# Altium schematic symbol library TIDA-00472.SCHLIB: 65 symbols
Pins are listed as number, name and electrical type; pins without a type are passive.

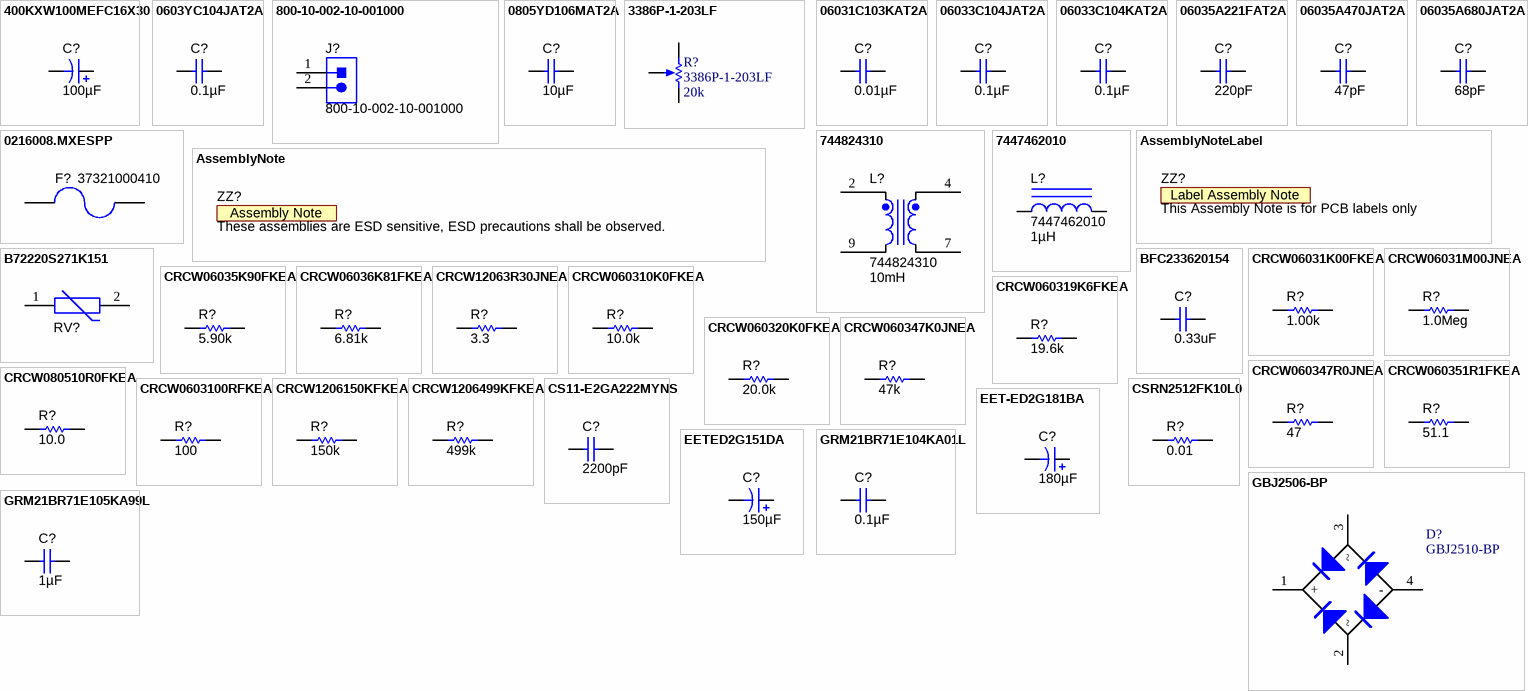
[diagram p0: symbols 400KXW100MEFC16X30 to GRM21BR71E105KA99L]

## 400KXW100MEFC16X30
designator C?  ValueDisplayed: 100µF  (hidden comment: 400KXW100MEFC16X30)
CAP, AL, 100 µF, 400 V, +/- 20%, TH; Manufacturer: Rubycon; Polarized: Y; CompType: Capacitor; Value: 100uF; U/M: EA; Cap_F: 0.0001; Tolerance_%: 20; Value1: Unknown; VDC_V: 400; Value2: 400V; IRMS_A: 0.58; TaMin_C: -25; TaMax_C: 105; Cap_Case: RCAP, 16x30mm
signal-integrity model Cap
simulation model Cap
footprint CAPPR750W80D1600H3000
footprint CAPPR750W80D1600H3000_HU
footprint CAPPR750W80D1600H3000_HD
pins: 1 +, 2 -

## 0603YC104JAT2A
designator C?  ValueDisplayed: 0.1µF  (hidden comment: 0603YC104JAT2A)
CAP, CERM, 0.1uF, 16V, +/-5%, X7R, 0603; Manufacturer: AVX; Polarized: N; CompType: Capacitor; U/M: EA; Cap_F: 0.0000001; Tolerance_%: 5; ESR_Ohm: 0.039; Value1: 0.039 ohm; VDC_V: 16; TaMin_C: -55; TaMax_C: 125; Cap_Case: 0603
signal-integrity model Cap
simulation model Cap
footprint 0603
footprint 0603M
footprint 0603L
footprint 0603_HV
footprint 0603S
pins: 1, 2

## 800-10-002-10-001000
designator J?
Header, 100mil, 2x1, TH; Manufacturer: Mill-Max; SymbolCreator: a0412235; U/M: EA
footprint Mill-Max_800-10-002-10-001000
pins: 1, 2
1 alternate drawing of the same symbol

## 0805YD106MAT2A
designator C?  ValueDisplayed: 10µF  (hidden comment: 0805YD106MAT2A)
CAP, CERM, 10uF, 16V, +/-20%, X5R, 0805; Manufacturer: AVX; Polarized: N; CompType: Capacitor; U/M: EA; Cap_F: 0.00001; Tolerance_%: 20; Value1: Unknown; VDC_V: 16; TaMin_C: -55; TaMax_C: 85; Cap_Case: 0805
signal-integrity model Cap
simulation model Cap
footprint 0805_HV
footprint 0805
footprint 0805M
footprint 0805L
pins: 1, 2

## 3386P-1-203LF
designator R?  value 20k
TRIMMER, 20k ohm, 0.5W, TH; Manufacturer: Bourns; Sim Note: Enter the Resistance value and the set point into parameter fields.; SymbolCreator: a0412235
simulation model POT (Potentiometer)
footprint BOURNS_3386P
pins: 1 CCW, 2 WIPER, 3 CW
1 alternate drawing of the same symbol

## 06031C103KAT2A
designator C?  ValueDisplayed: 0.01µF  (hidden comment: 06031C103KAT2A)
CAP, CERM, 0.01uF, 100V, +/-10%, X7R, 0603; Manufacturer: AVX; Polarized: N; CompType: Capacitor; U/M: EA; Cap_F: 0.00000001; Tolerance_%: 10; ESR_Ohm: 0.098; Value1: 0.098 ohm; VDC_V: 100; TaMin_C: -55; TaMax_C: 125; Cap_Case: 0603
signal-integrity model Cap
simulation model Cap
footprint 0603
footprint 0603M
footprint 0603L
footprint 0603_HV
footprint 0603S
pins: 1, 2

## 06033C104JAT2A
designator C?  ValueDisplayed: 0.1µF  (hidden comment: 06033C104JAT2A)
CAP, CERM, 0.1uF, 25V, +/-5%, X7R, 0603; Manufacturer: AVX; Polarized: N; CompType: Capacitor; U/M: EA; Cap_F: 0.0000001; Tolerance_%: 5; ESR_Ohm: 0.05; Value1: 0.05 ohm; VDC_V: 25; TaMin_C: -55; TaMax_C: 125; Cap_Case: 0603
signal-integrity model Cap
simulation model Cap
footprint 0603
footprint 0603M
footprint 0603L
footprint 0603_HV
footprint 0603S
pins: 1, 2

## 06033C104KAT2A
designator C?  ValueDisplayed: 0.1µF  (hidden comment: 06033C104KAT2A)
CAP, CERM, 0.1 µF, 25 V, +/- 10%, X7R, 0603; Manufacturer: AVX; Polarized: N; CompType: Capacitor; Value: 0.1uF; U/M: EA; Cap_F: 0.0000001; Tolerance_%: 10; ESR_ohm: 0.05; Value1: 0.05 ohm; VDC_V: 25; Value2: 25V; TaMin_C: -55; TaMax_C: 125; Cap_Case: 0603
signal-integrity model Cap
simulation model Cap
footprint 0603
footprint 0603M
footprint 0603L
footprint 0603_HV
footprint 0603S
pins: 1, 2

## 06035A221FAT2A
designator C?  ValueDisplayed: 220pF  (hidden comment: 06035A221FAT2A)
CAP, CERM, 220 pF, 50 V, +/- 1%, C0G/NP0, 0603; Manufacturer: AVX; Polarized: N; CompType: Capacitor; Value: 220pF; U/M: EA; Cap_F: 0.00000000022; Tolerance_%: 1; ESR_ohm: 0.083; Value1: 0.083 ohm; VDC_V: 50; Value2: 50V; TaMin_C: -55; TaMax_C: 125; Cap_Case: 0603
signal-integrity model Cap
simulation model Cap
footprint 0603
footprint 0603M
footprint 0603L
footprint 0603_HV
footprint 0603S
pins: 1, 2

## 06035A470JAT2A
designator C?  ValueDisplayed: 47pF  (hidden comment: 06035A470JAT2A)
CAP, CERM, 47 pF, 50 V, +/- 5%, C0G/NP0, 0603; Manufacturer: AVX; Polarized: N; CompType: Capacitor; Value: 47pF; U/M: EA; Cap_F: 0.000000000047; Tolerance_%: 5; ESR_ohm: 0.174; Value1: 0.174 ohm; VDC_V: 50; Value2: 50V; TaMin_C: -55; TaMax_C: 125; Cap_Case: 0603
signal-integrity model Cap
simulation model Cap
footprint 0603
footprint 0603M
footprint 0603L
footprint 0603_HV
footprint 0603S
pins: 1, 2

## 06035A680JAT2A
designator C?  ValueDisplayed: 68pF  (hidden comment: 06035A680JAT2A)
CAP, CERM, 68pF, 50V, +/-5%, C0G/NP0, 0603; Manufacturer: AVX; Polarized: N; CompType: Capacitor; U/M: EA; Cap_F: 0.000000000068; Tolerance_%: 5; ESR_Ohm: 0.144; Value1: 0.144 ohm; VDC_V: 50; TaMin_C: -55; TaMax_C: 125; Cap_Case: 0603
signal-integrity model Cap
simulation model Cap
footprint 0603
footprint 0603M
footprint 0603L
footprint 0603_HV
footprint 0603S
pins: 1, 2

## 0216008.MXESPP
designator F?, comment 37321000410
FUSE BOARD MNT 10A 250VAC RADIAL; Manufacturer: Littelfuse Inc; U/M: EA; VDC_V: 250; Irating_A: 8; Rtyp_Ohm: 0.0123; Soldering_Wave_MaxTemp_C: 260; Soldering_Wave_MaxTime_s: 5
footprint FUSE_37321000430 (LITTELFUSE_373, TH-2P)
footprint CAPPRD1000W150D3500H5000 (Panasonic)
footprint CAPPR2-5x11 (Capacitor, Electrolytic, Radial; Body 5 x 11 mm (Dia.xH typ); Pin Spacing 2 mm (typ))
pins: 1, 2

## 744824310
designator L?  ValueDisplayed: 10mH
Coupled inductor, 10 mH, 3 A, 0.105 ohm, +/- 30%, TH; Manufacturer: Wurth Elektronik eiSos; SymbolCreator: a0799628; Ind_H: 10.0E-3; DCR_ohm: 0.105; Isat: 3; Tolerance_%: 30; Value: 10mH
footprint IND_WE-CMB_L
pins: 2, 4, 7, 9

## 7447462010
designator L?  ValueDisplayed: 1µH
Inductor, Unshielded Drum Core, Ferrite, 1uH, 8A, 0.006 ohm, TH; Manufacturer: Wurth Elektronik eiSos; Ind_H: 1.0E-6; Imax_A: 8; Irms: 8.5A @ 40C rise; Isat: 8A @ 10% inductance drop; DCR_ohm: 0.006; U/M: EA
signal-integrity model Inductor
simulation model Inductor
footprint IND_WE-TI_XS
footprint CAPPRD1000W150D3500H5000 (Panasonic)
footprint CAPPR2-5x11 (Capacitor, Electrolytic, Radial; Body 5 x 11 mm (Dia.xH typ); Pin Spacing 2 mm (typ))
pins: 1, 2

## AssemblyNote
designator ZZ?, comment These assemblies are ESD sensitive, ESD precautions shall be observed.  (no BOM)
SymbolCreator: codlsc; CompType: AssemblyNote
footprint AssemblyNote

## AssemblyNoteLabel
designator ZZ?, comment This Assembly Note is for PCB labels only  (no BOM)
SymbolCreator: a0412235
footprint AssemblyNoteLabel

## B72220S271K151
designator RV?  (value not drawn)
VARISTOR, 387V, 8KA, DISC 20MM; Manufacturer: EPCOS Inc; SymbolCreator: x0199378
footprint VAR_B72220S0271K151 (VARISTOR, 275V, 8KA, DISC 20MM)
footprint VAR_B72220S0271K151 (VARISTOR, 275V, 8KA, DISC 20MM)
pins: 1, 2

## BFC233620154
designator C?, comment value 0.33uF  (hidden comment: B32922C3334M189)
CAP FILM 0.33UF 630VDC RADIAL; Manufacturer: EPCOS(TDK); CompType: Film Capacitor; SymbolCreator: x0199378
footprint B32922_12mm (Epcos film capacitors, 15mm spacing)
pins: 1, 2

## CRCW06031K00FKEA
designator R?  ValueDisplayed: 1.00k  (hidden comment: CRCW06031K00FKEA)
RES, 1.00 k, 1%, 0.1 W, 0603; Manufacturer: Vishay-Dale; CompType: Resistor; Value: 1.00k; Res_ohm: 1000; Value_Code: 1k00; Tolerance_%: 1; Power_W: 0.1; Value2: 0.1W; VDC_V: 75; TempCo: 100 ppm/C; EIA_Code: E96; U/M: EA
signal-integrity model Resistor
simulation model Resistor
footprint 0603
footprint 0603M
footprint 0603L
footprint 0603_HV
footprint 0603S
pins: 1, 2

## CRCW06031M00JNEA
designator R?  value 1.0Meg  (hidden comment: CRCW06031M00JNEA)
RES, 1.0Meg ohm, 5%, 0.1W, 0603; Manufacturer: Vishay-Dale; CompType: Resistor; Res_ohm: 1000000; Value_Code: 1M00; Tolerance_%: 5; Power_W: 0.1; VDC_V: 75; TempCo: 200 ppm/C; EIA_Code: E24; U/M: EA
signal-integrity model Resistor
simulation model Resistor
footprint 0603
footprint 0603M
footprint 0603L
footprint 0603_HV
footprint 0603S
pins: 1, 2

## CRCW06035K90FKEA
designator R?  ValueDisplayed: 5.90k  (hidden comment: CRCW06035K90FKEA)
RES, 5.90 k, 1%, 0.1 W, 0603; Manufacturer: Vishay-Dale; CompType: Resistor; Res_ohm: 5900; Value: 5.90k; Value_Code: 5k90; Tolerance_%: 1; Power_W: 0.1; Value2: 0.1W; VDC_V: 75; TempCo: 100 ppm/C; EIA_Code: E96; U/M: EA
signal-integrity model Resistor
simulation model Resistor
footprint 0603
footprint 0603M
footprint 0603L
footprint 0603_HV
footprint 0603S
pins: 1, 2

## CRCW06036K81FKEA
designator R?  ValueDisplayed: 6.81k  (hidden comment: CRCW06036K81FKEA)
RES, 6.81 k, 1%, 0.1 W, 0603; Manufacturer: Vishay-Dale; CompType: Resistor; Value: 6.81k; Res_ohm: 6810; Value_Code: 6k81; Tolerance_%: 1; Power_W: 0.1; Value2: 0.1W; VDC_V: 75; TempCo: 100 ppm/C; EIA_Code: E96; U/M: EA
signal-integrity model Resistor
simulation model Resistor
footprint 0603
footprint 0603M
footprint 0603L
footprint 0603_HV
footprint 0603S
pins: 1, 2

## CRCW12063R30JNEA
designator R?  value 3.3  (hidden comment: CRCW12063R30JNEA)
RES, 3.3 ohm, 5%, 0.25W, 1206; Manufacturer: Vishay-Dale; CompType: Resistor; Value_Code: 3R30; Tolerance_%: 5; Power_W: 0.25; VDC_V: 200; TempCo: 200 ppm/C; EIA_Code: E24; U/M: EA
signal-integrity model Resistor
simulation model Resistor
footprint 1206
footprint 1206M
footprint 1206L
pins: 1, 2

## CRCW060310K0FKEA
designator R?  ValueDisplayed: 10.0k  (hidden comment: CRCW060310K0FKEA)
RES, 10.0 k, 1%, 0.1 W, 0603; Manufacturer: Vishay-Dale; CompType: Resistor; Value: 10.0k; Res_ohm: 10000; Value_Code: 10k0; Tolerance_%: 1; Power_W: 0.1; Value2: 0.1W; VDC_V: 75; TempCo: 100 ppm/C; EIA_Code: E96; U/M: EA
signal-integrity model Resistor
simulation model Resistor
footprint 0603
footprint 0603M
footprint 0603L
footprint 0603_HV
footprint 0603S
pins: 1, 2

## CRCW060319K6FKEA
designator R?  ValueDisplayed: 19.6k  (hidden comment: CRCW060319K6FKEA)
RES, 19.6 k, 1%, 0.1 W, 0603; Manufacturer: Vishay-Dale; CompType: Resistor; Value: 19.6k; Res_ohm: 19600; Value_Code: 19k6; Tolerance_%: 1; Power_W: 0.1; Value2: 0.1W; VDC_V: 75; TempCo: 100 ppm/C; EIA_Code: E96; U/M: EA
signal-integrity model Resistor
simulation model Resistor
footprint 0603
footprint 0603M
footprint 0603L
footprint 0603_HV
footprint 0603S
pins: 1, 2

## CRCW060320K0FKEA
designator R?  value 20.0k  (hidden comment: CRCW060320K0FKEA)
RES, 20.0k ohm, 1%, 0.1W, 0603; Manufacturer: Vishay-Dale; CompType: Resistor; Res_ohm: 20000; Value_Code: 20k0; Tolerance_%: 1; Power_W: 0.1; VDC_V: 75; TempCo: 100 ppm/C; EIA_Code: E96; U/M: EA
signal-integrity model Resistor
simulation model Resistor
footprint 0603
footprint 0603M
footprint 0603L
footprint 0603_HV
footprint 0603S
pins: 1, 2

## CRCW060347K0JNEA
designator R?  value 47k  (hidden comment: CRCW060347K0JNEA)
RES, 47k ohm, 5%, 0.1W, 0603; Manufacturer: Vishay-Dale; CompType: Resistor; Res_ohm: 47000; Value_Code: 47k0; Tolerance_%: 5; Power_W: 0.1; VDC_V: 75; TempCo: 200 ppm/C; EIA_Code: E24; U/M: EA
signal-integrity model Resistor
simulation model Resistor
footprint 0603
footprint 0603M
footprint 0603L
footprint 0603_HV
footprint 0603S
pins: 1, 2

## CRCW060347R0JNEA
designator R?  ValueDisplayed: 47  (hidden comment: CRCW060347R0JNEA)
RES, 47, 5%, 0.1 W, 0603; Manufacturer: Vishay-Dale; CompType: Resistor; Value: 47; Value_Code: 47R0; Tolerance_%: 5; Power_W: 0.1; Value2: 0.1W; VDC_V: 75; TempCo: 200 ppm/C; EIA_Code: E24; U/M: EA
signal-integrity model Resistor
simulation model Resistor
footprint 0603
footprint 0603M
footprint 0603L
footprint 0603_HV
footprint 0603S
pins: 1, 2

## CRCW060351R1FKEA
designator R?  ValueDisplayed: 51.1  (hidden comment: CRCW060351R1FKEA)
RES, 51.1, 1%, 0.1 W, 0603; Manufacturer: Vishay-Dale; CompType: Resistor; Value: 51.1; Value_Code: 51R1; Tolerance_%: 1; Power_W: 0.1; Value2: 0.1W; VDC_V: 75; TempCo: 100 ppm/C; EIA_Code: E96; U/M: EA
signal-integrity model Resistor
simulation model Resistor
footprint 0603
footprint 0603M
footprint 0603L
footprint 0603_HV
footprint 0603S
pins: 1, 2

## CRCW080510R0FKEA
designator R?  ValueDisplayed: 10.0  (hidden comment: CRCW080510R0FKEA)
RES, 10.0, 1%, 0.125 W, 0805; Manufacturer: Vishay-Dale; CompType: Resistor; Value: 10.0; Res_ohm: 10; Value_Code: 10R0; Tolerance_%: 1; Power_W: 0.125; Value2: 0.125W; VDC_V: 150; TempCo: 100 ppm/C; EIA_Code: E96; U/M: EA
signal-integrity model Resistor
simulation model Resistor
footprint 0805_HV
footprint 0805
footprint 0805M
footprint 0805L
pins: 1, 2

## CRCW0603100RFKEA
designator R?  ValueDisplayed: 100  (hidden comment: CRCW0603100RFKEA)
RES, 100, 1%, 0.1 W, 0603; Manufacturer: Vishay-Dale; CompType: Resistor; Value: 100; Value_Code: 100R; Tolerance_%: 1; Power_W: 0.1; Value2: 0.1W; VDC_V: 75; TempCo: 100 ppm/C; EIA_Code: E96; U/M: EA
signal-integrity model Resistor
simulation model Resistor
footprint 0603
footprint 0603M
footprint 0603L
footprint 0603_HV
footprint 0603S
pins: 1, 2

## CRCW1206150KFKEA
designator R?  value 150k  (hidden comment: CRCW1206150KFKEA)
RES, 150k ohm, 1%, 0.25W, 1206; Manufacturer: Vishay-Dale; CompType: Resistor; Res_ohm: 150000; Tolerance_%: 1; Power_W: 0.25; VDC_V: 200; TempCo: 100 ppm/C; EIA_Code: E96; U/M: EA
signal-integrity model Resistor
simulation model Resistor
footprint 1206 (1206 from SM-752 data)
footprint 1206M
footprint 1206L
pins: 1, 2

## CRCW1206499KFKEA
designator R?  value 499k  (hidden comment: CRCW1206499KFKEA)
RES, 499k ohm, 1%, 0.25W, 1206; Manufacturer: Vishay-Dale; CompType: Resistor; Res_ohm: 499000; Tolerance_%: 1; Power_W: 0.25; VDC_V: 200; TempCo: 100 ppm/C; EIA_Code: E96; U/M: EA
signal-integrity model Resistor
simulation model Resistor
footprint 1206
footprint 1206M
footprint 1206L
pins: 1, 2

## CS11-E2GA222MYNS
designator C?  ValueDisplayed: 2200pF  (hidden comment: CS11-E2GA222MYNS)
CAP, CERM, 2200 pF, 250 V, +/- 20%, E, Radial Disc D10.5x7mm; Manufacturer: TDK; Polarized: N; CompType: Capacitor; Value: 2200pF; U/M: EA; Cap_F: 0.0000000022; Tolerance_%: 20; Value1: Unknown; VDC_V: 250; Value2: 250V; TaMin_C: -25; TaMax_C: 105; Cap_Case: Disc, 10.5x7mm
signal-integrity model Cap
simulation model Cap
footprint CAPRD750W60D1050H1450
pins: 1, 2

## CSRN2512FK10L0
designator R?  value 0.01  (hidden comment: CSRN2512FK10L0)
RES, 0.01 ohm, 1%, 2W, 2512; Manufacturer: Stackpole Electronics Inc; CompType: Resistor; Value_Code: R010; Tolerance_%: 1; Power_W: 2; TempCo: 200 ppm/C; EIA_Code: E96; U/M: EA
signal-integrity model Resistor
simulation model Resistor
footprint 2512
footprint 2512M
footprint 2512L
pins: 1, 2

## EET-ED2G181BA
designator C?  ValueDisplayed: 180µF  (hidden comment: EET-ED2G181BA)
CAP, AL, 180 µF, 400 V, +/- 20%, 0.737 ohm, TH; Manufacturer: Panasonic; Polarized: Y; CompType: Capacitor; Value: 180uF; U/M: EA; Cap_F: 0.00018; Tolerance_%: 20; VDC_V: 400; Value2: 400V; ESR_ohm: 0.737; IRMS_A: 1.12; TaMin_C: -25; TaMax_C: 105; Cap_Case: Radial 10-22x45
signal-integrity model Cap
simulation model Cap
footprint CAPPR10-22x45
pins: 1 +, 2 -

## EETED2G151DA
designator C?  ValueDisplayed: 150µF  (hidden comment: EETED2G151DA)
CAP, AL, 150 µF, 400 V, +/- 20%, 0.884 ohm, TH; Manufacturer: Panasonic; Polarized: Y; CompType: Capacitor; Value: 150uF; U/M: EA; Cap_F: 0.00015; Tolerance_%: 20; VDC_V: 400; Value2: 400V; ESR_ohm: 0.884; IRMS_A: 1.05; TaMin_C: -25; TaMax_C: 105; Cap_Case: 30x25
signal-integrity model Cap
simulation model Cap
footprint CAPPR10-30x25
pins: 1 +, 2 -

## GBJ2506-BP
designator D?, comment GBJ2510-BP
RECT BRIDGE GPP 25A 1000V GBJ; Manufacturer: MICRO COMMERCIAL COMPONENTS; CompType: Bridge Rectifier; SymbolCreator: x0199378
footprint MCC_GBJ2506 (Bridge Rectifier, 4pin , TH)
footprint MCC_GBJ2506 (Bridge Rectifier, 4pin , TH)
pins: 1 +, 2 ~, 3 ~, 4 -

## GRM21BR71E104KA01L
designator C?  ValueDisplayed: 0.1µF  (hidden comment: GRM21BR71E104KA01L)
CAP, CERM, 0.1 µF, 25 V, +/- 10%, X7R, 0805; Manufacturer: MuRata; Polarized: N; CompType: Capacitor; Value: 0.1uF; U/M: EA; Cap_F: 0.0000001; Tolerance_%: 10; Value1: Unknown; VDC_V: 25; Value2: 25V; TaMin_C: -55; TaMax_C: 125; Cap_Case: 0805
signal-integrity model Cap
simulation model Cap
footprint 0805_HV
footprint 0805
footprint 0805M
footprint 0805L
pins: 1, 2

## GRM21BR71E105KA99L
designator C?  ValueDisplayed: 1µF  (hidden comment: GRM21BR71E105KA99L)
CAP, CERM, 1uF, 25V, +/-10%, X7R, 0805; Manufacturer: MuRata; Polarized: N; CompType: Capacitor; U/M: EA; Cap_F: 0.000001; Tolerance_%: 10; Value1: Unknown; VDC_V: 25; TaMin_C: -55; TaMax_C: 125; Cap_Case: 0805
signal-integrity model Cap
simulation model Cap
footprint 0805_HV
footprint 0805
footprint 0805M
footprint 0805L
pins: 1, 2

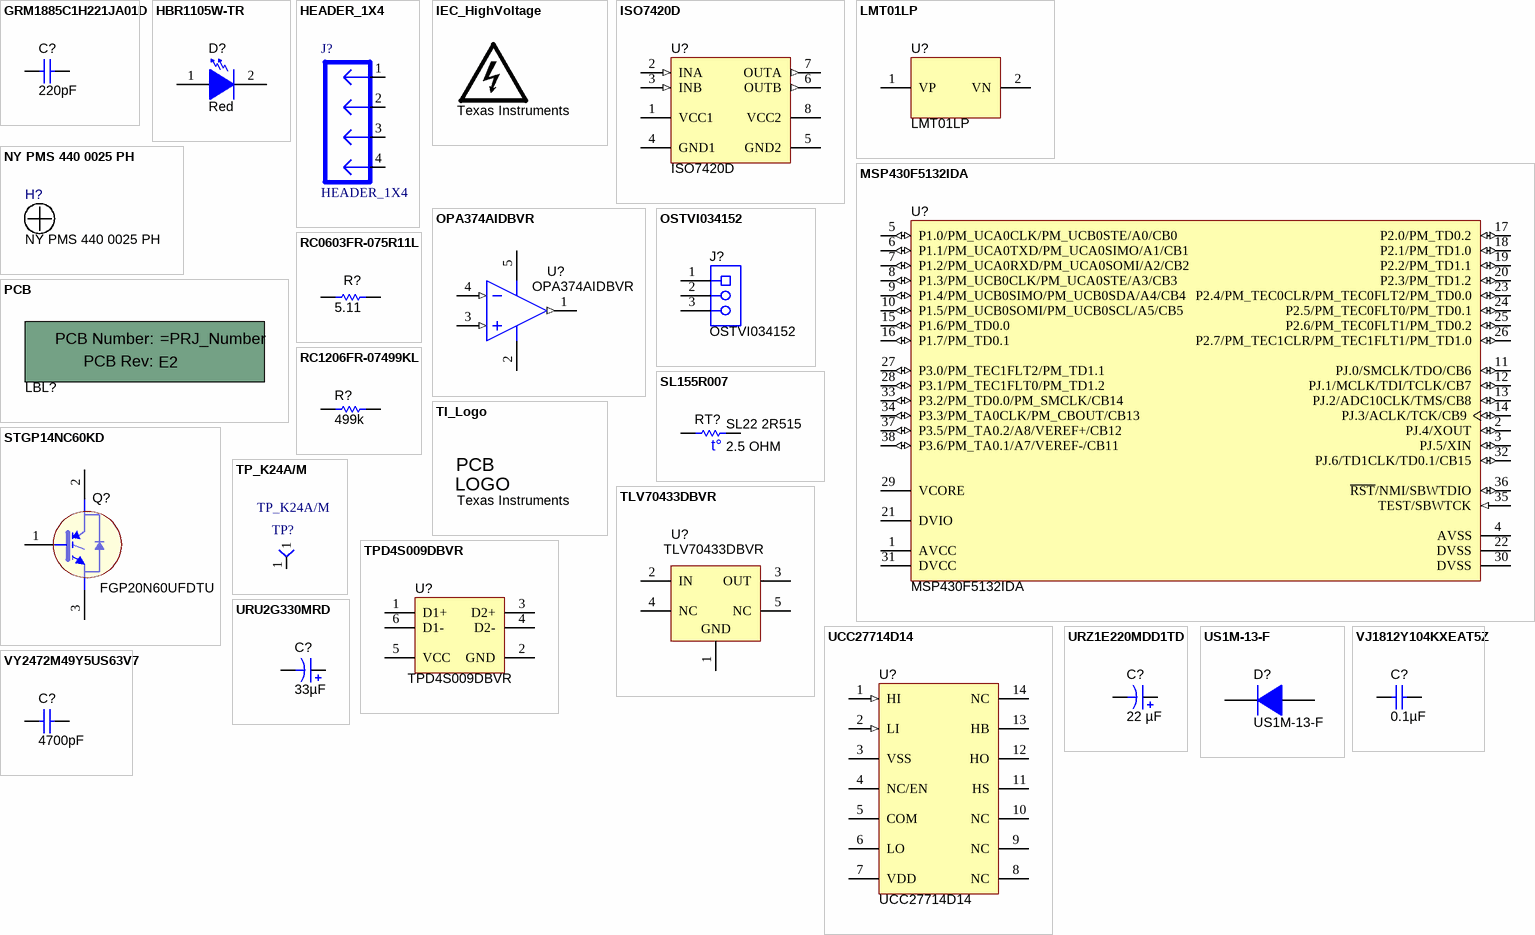
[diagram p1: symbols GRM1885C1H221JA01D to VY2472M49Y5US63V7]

## GRM1885C1H221JA01D
designator C?  ValueDisplayed: 220pF  (hidden comment: GRM1885C1H221JA01D)
CAP, CERM, 220 pF, 50 V, +/- 5%, C0G/NP0, 0603; Manufacturer: MuRata; Polarized: N; CompType: Capacitor; Value: 220pF; U/M: EA; Cap_F: 0.00000000022; Tolerance_%: 5; Value1: Unknown; VDC_V: 50; Value2: 50V; TaMin_C: -55; TaMax_C: 125; Cap_Case: 0603
signal-integrity model Cap
simulation model Cap
footprint 0603
footprint 0603M
footprint 0603L
footprint 0603_HV
footprint 0603S
pins: 1, 2

## HBR1105W-TR
designator D?  value Red  (hidden comment: HBR1105W-TR)
LED, Red, SMD; Manufacturer: Stanley Electric Co., LTD; Vf_V: 1.7; Value2: 1.7V; Io_A: 0.02; Value1: W; U/M: EA
signal-integrity model Diode
footprint 1105W_Red
pins: 1 A, 2 K

## HEADER_1X4
designator J?
Header, Male 4-pin, 100mil spacing,; Manufacturer: Sullins; PartNumber: PEC04SAAN; area: 44000; Value: PEC04SAAN
footprint HDR100_1X4
footprint Mill-Max_800-10-004-10-001000 (Mill-Max)
pins: 1, 2, 3, 4

## IEC_HighVoltage
designator LOGO?, comment Texas Instruments  (no BOM)
IEC 61010-1 High Voltage Warning; SymbolCreator: a0412235
footprint IEC_HighVoltage_Large
footprint IEC_HighVoltage_Medium
footprint IEC_HighVoltage_Small
footprint TI_Stacked_SolderMask_Small

## ISO7420D
designator U?
1 Mbps Low Power Dual Channels Isolator, 3.3 V / 5 V, -40 to +105 degC, 8-pin SOIC (D), Green (RoHS & no Sb/Br); Manufacturer: Texas Instruments; Alternate PartNumber: Equivalent; Datarate(Mbps): 1; Input Noise Filter: None; Insulation Rating(VRMS): 2500; Prop Delay(Max)(ns): 12; Rating: Catalog; Supply Voltage(s)(V): 3.3, 5; TTL/CMOS Input Threshold: TTL
footprint D0008A_N (SOIC, 8-Leads, Body 5x4mm, Pitch 1.27mm, IPC Medium Density)
footprint D0008A_L (SOIC, 8-Leads, Body 5x4mm, Pitch 1.27mm, IPC High Density)
footprint D0008A_M (SOIC, 8-Leads, Body 5x4mm, Pitch 1.27mm, IPC Low Density)
pins: 1 VCC1 (power) "Power supply, VCC1", 2 INA (in) "Input, channel A", 3 INB (in) "Input, channel B", 4 GND1 (power) "Ground connection for VCC1", 5 GND2 (power) "Ground connection for VCC2", 6 OUTB (out) "Output, channel B", 7 OUTA (out) "Output, channel A", 8 VCC2 (power) "Power supply, VCC2"

## LMT01LP
designator U?
High-Accuracy 2-pin Temperature Sensor with a Pulsed-Current Interface, LP0002A; Manufacturer: Texas Instruments; SymbolCreator: a0799628; CompType: IC; U/M: EA
footprint LP0002A (TO-92, 2 pins Inline)
pins: 1 VP (power), 2 VN

## MSP430F5132IDA
designator U?
25 MHz Mixed Signal Microcontroller with 8 KB Flash, 1024 B SRAM and 29 GPIOs, -40 to 85 degC, 38-pin SOP (DA), Green (RoHS & no Sb/Br); Alternate Manufacturer: Texas Instruments; Alternate PartNumber: Equivalent; ADC: 10-bit SAR; ADC Channels: 8; Brown Out Reset: Yes; DMA: 3; Frequency(MHz): 25; GPIO: 29; Multiplier: 32x32; Pin/Package: 38TSSOP, 40WQFN; SRAM(B): 1024; SubFamily: 5 Series; USCI_A (UART/LIN/IrDA/SPI): 1
footprint DA0038A_N (SOP, 38-Leads, Body 12.5x6.1mm, Pitch 0.65mm, IPC Medium Density)
footprint DA0038A_L (SOP, 38-Leads, Body 12.5x6.1mm, Pitch 0.65mm, IPC High Density)
footprint DA0038A_M (SOP, 38-Leads, Body 12.5x6.1mm, Pitch 0.65mm, IPC Low Density)
pins: 1 AVCC (power) "Analog power supply", 2 PJ.4/XOUT (io), 3 PJ.5/XIN (io), 4 AVSS (power) "Analog ground supply", 5 P1.0/PM_UCA0CLK/PM_UCB0STE/A0/CB0 (io), 6 P1.1/PM_UCA0TXD/PM_UCA0SIMO/A1/CB1 (io), 7 P1.2/PM_UCA0RXD/PM_UCA0SOMI/A2/CB2 (io), 8 P1.3/PM_UCB0CLK/PM_UCA0STE/A3/CB3 (io), 9 P1.4/PM_UCB0SIMO/PM_UCB0SDA/A4/CB4 (io), 10 P1.5/PM_UCB0SOMI/PM_UCB0SCL/A5/CB5 (io), 11 PJ.0/SMCLK/TDO/CB6 (io), 12 PJ.1/MCLK/TDI/TCLK/CB7 (io), 13 PJ.2/ADC10CLK/TMS/CB8 (io), 14 PJ.3/ACLK/TCK/CB9 (io), 15 P1.6/PM_TD0.0 (io), 16 P1.7/PM_TD0.1 (io), 17 P2.0/PM_TD0.2 (io), 18 P2.1/PM_TD1.0 (io), 19 P2.2/PM_TD1.1 (io), 20 P2.3/PM_TD1.2 (io), 21 DVIO (power) "5V tolerant digital I/O power supply", 22 DVSS (power) "Digital ground supply", 23 P2.4/PM_TEC0CLR/PM_TEC0FLT2/PM_TD0.0 (io), 24 P2.5/PM_TEC0FLT0/PM_TD0.1 (io), 25 P2.6/PM_TEC0FLT1/PM_TD0.2 (io), 26 P2.7/PM_TEC1CLR/PM_TEC1FLT1/PM_TD1.0 (io), 27 P3.0/PM_TEC1FLT2/PM_TD1.1 (io), 28 P3.1/PM_TEC1FLT0/PM_TD1.2 (io), 29 VCORE "Regulated core power supply", 30 DVSS (power) "Digital ground supply", 31 DVCC (power) "Digital power supply", 32 PJ.6/TD1CLK/TD0.1/CB15 (io), 33 P3.2/PM_TD0.0/PM_SMCLK/CB14 (io), 34 P3.3/PM_TA0CLK/PM_CBOUT/CB13 (io), 35 TEST/SBWTCK (in), 36 ~{RST}/NMI/SBWTDIO (io), 37 P3.5/PM_TA0.2/A8/VEREF+/CB12 (io), 38 P3.6/PM_TA0.1/A7/VEREF-/CB11 (io)

## NY PMS 440 0025 PH
designator H?
MACHINE SCREW PAN SLOTTED M3; Manufacturer: Keystone Electronics; PartNumber: 29344; CompType: Hardware; SymbolCreator: codlsc; U/M: EA
footprint NY PMS 440 0025 PH
footprint NY PMS 440 0025 PH_3Donly

## OPA374AIDBVR
designator U?
6.5 MHz, 585 uA, Rail-to-Rail I/O CMOS Operational Amplifier, 2.3 to 5.5 V, -40 to 125 degC, 5-pin SOT23 (DBV0005A), Green (RoHS & no Sb/Br); Manufacturer: Texas Instruments; Alternate Manufacturer: None; Alternate PartNumber: Equivalent; CMRR(Min)(dB): 80; GBW(Typ)(MHz): 6.5; IIB(Max)(pA): 10; Iq per channel(Max)(mA): 0.75; Number of Channels: 1; Offset Drift(Typ)(uV/C): 3; Packing: LARGE T&R; Rating: Catalog; Slew Rate(Typ)(V/us): 5; Sub Family: High Output Current Amplifier (>=50mA), Low Input Bias Current Amp (<=10pA), Low Supply Voltage Amplifier (<=2.7V), Precision Amplifier; Total Supply Voltage(Max)(+5V is 5, +/-5V is 10): 5.5; Total Supply Voltage(Min)(+5V is 5, +/-5V is 10): 2.3
footprint DBV0005A_N (SOT23, 5-Leads, Body 2.9x1.6mm, Pitch 0.95mm, IPC Medium Density)
footprint DBV0005A_L (SOT23, 5-Leads, Body 2.9x1.6mm, Pitch 0.95mm, IPC Low Density)
footprint DBV0005A_M (SOT23, 5-Leads, Body 2.9x1.6mm, Pitch 0.95mm, IPC Low Density)
pins: 1 OUT (out), 2 V- (power), 3 IN+ (in), 4 IN- (in), 5 V+ (power)

## OSTVI034152
designator J?
TERMINAL BLOCK 7.50MM 3POS PCB, TH; Manufacturer: On-Shore Technology; SymbolCreator: x0199378
footprint ONSHORE_OSTVI034152 (TERMINAL BLOCK, 7.5MM PITCH,THRU-3PINS)
pins: 1, 2, 3

## PCB
designator LBL?, comment Printed Circuit Board  (value not drawn)  (mechanical)
Manufacturer: Any; SymbolCreator: a0412235; CompType: PCB
footprint Label_650x200 (Thermal Transfer Label)
1 alternate drawing of the same symbol

## RC0603FR-075R11L
designator R?  ValueDisplayed: 5.11  (hidden comment: RC0603FR-075R11L)
RES, 5.11, 1%, 0.1 W, 0603; Manufacturer: Yageo America; CompType: Resistor; Value: 5.11; Value_Code: 5R11; Tolerance_%: 1; Power_W: 0.1; Value2: 0.1W; VDC_V: 150; TempCo: 200 ppm/C; EIA_Code: E96; U/M: EA
signal-integrity model Resistor
simulation model Resistor
footprint 0603
footprint 0603M
footprint 0603L
footprint 0603_HV
footprint 0603S
pins: 1, 2

## RC1206FR-07499KL
designator R?  ValueDisplayed: 499k  (hidden comment: RC1206FR-07499KL)
RES, 499 k, 1%, 0.25 W, 1206; Manufacturer: Yageo America; CompType: Resistor; Value: 499k; Res_ohm: 499000; Tolerance_%: 1; Power_W: 0.25; Value2: 0.25W; VDC_V: 200; TempCo: 100 ppm/C; EIA_Code: E96; U/M: EA
signal-integrity model Resistor
simulation model Resistor
footprint 1206
footprint 1206M
footprint 1206L
pins: 1, 2

## SL155R007
designator RT?, comment SL22 2R515  value 2.5 OHM
CURRENT LIMITR INRSH 2.5 OHM 15A; Manufacturer: AMETHERM; CompType: ThermistorNTC; SymbolCreator: x0199378
footprint THERM_B57364S0 (CURRENT LIMITER INRUSH, 2 PIN, TH, EPCOS)
footprint THERM_B57364S0 (CURRENT LIMITER INRUSH, 2 PIN, TH, EPCOS)
pins: 1, 2

## STGP14NC60KD
designator Q?, comment FGP20N60UFDTU
IC, IGBT, 600V, 25A, 80W, TO-220; Manufacturer: ST MICRO ELECTRONICS; CompType: IGBT, POWER MESH; SymbolCreator: x0199378
footprint TO-220_HSK_581002B00000 (TO-220A, 2.54MM PITCH,THRU-3PINS WITH HEAT SINK)
footprint TO-220AB (Copied from Altium's version of TO3B)
pins: 1 G, 2 C, 3 E

## TI_Logo
designator Logo?, comment Texas Instruments  (no BOM)
Texas Instrument Corporate Signature; SymbolCreator: codlsc
footprint TI_Stacked_SolderMask_Medium
footprint TI_Stacked_Overlay_Small
footprint TI_Stacked_Overlay_Medium
footprint TI_Stacked_Overlay_Small
footprint TI_Horizontal_SolderMask_Medium
footprint TI_Horizontal_SolderMask_Small
footprint TI_Horizontal_Overlay_Medium
footprint TI_Horizontal_Overlay_Small
footprint TI_Symbol_SolderMask_Small
footprint TI_Symbol_Overlay_Medium
footprint TI_Symbol_Overlay_Small
footprint TI_Symbol_SolderMask_Medium

## TLV70433DBVR
designator U?
Single Output LDO, 150 mA, Fixed 3.3 V Output, 2.5 to 24 V Input, with Ultra-Low IQ, 5-pin SOT-23 (DBV), -40 to 125 degC, Green (RoHS & no Sb/Br); Manufacturer: Texas Instruments; Alternate Manufacturer: None; Alternate PartNumber: Equivalent; Accuracy(%): 2; Fixed Output Options(V): 3.3; Iout(Max)(A): 0.15; Iq(Typ)(mA): 0.003; SubFamily: Single Channel LDO; Vdo(Typ)(mV): 400; Vin(Max)(V): 24; Vin(Min)(V): 2.5
footprint DBV0005A_N (SOT23, 5-Leads, Body 2.9x1.6mm, Pitch 0.95mm, IPC Medium Density)
footprint DBV0005A_L (SOT23, 5-Leads, Body 2.9x1.6mm, Pitch 0.95mm, IPC High Density)
footprint DBV0005A_M (SOT23, 5-Leads, Body 2.9x1.6mm, Pitch 0.95mm, IPC Low Density)
pins: 1 GND (power) "Ground", 2 IN (power) "Unregulated input voltage", 3 OUT (power) "Regulated output voltage. Any capacitor 1 uF or greater between this pin and ground is needed for stability", 4 NC "No connection. This pin can be left open or tied to ground for improved thermal performance", 5 NC "No connection. This pin can be left open or tied to ground for improved thermal performance"

## TP_K24A/M
designator TP?
Pin, Thru Hole, Tin Plate, for 0.062 PCB's; Manufacturer: Vector; PartNumber: K24A/M; area: 0.001 inch; Value: K24A/M
footprint HOLE-70X43
pins: 1

## TPD4S009DBVR
designator U?
ESD Solution for High-Speed Differential Interface, 4 Channels, -40 to +85 degC, 6-pin SOT-32 (DBV), Green (RoHS & no Sb/Br); Manufacturer: Texas Instruments; Alternate Manufacturer: None; Alternate PartNumber: Equivalent; Breakdown Voltage(Min)(V): 9; Differential Capacitance(pF): 0.05; IEC 61000-4-2 Contact(+/- kV): 8; IO Capacitance(Typ)(pF): 0.8; IO Leakage Current(nA): 10
footprint DBV0006A_N (SOT23, 6-Leads, Body 2.9x1.6mm, Pitch 0.95mm, Lead Span 2.8mm, IPC Medium Density)
footprint DBV0006A_L (SOT23, 6-Leads, Body 2.9x1.6mm, Pitch 0.95mm, Lead Span 2.8mm, IPC High Density)
footprint DBV0006A_M (SOT23, 6-Leads, Body 2.9x1.6mm, Pitch 0.95mm, Lead Span 2.8mm, IPC Low Density)
pins: 1 D1+ "High-speed ESD clamp provides ESD protection to the high-speed differential data line.", 2 GND (power) "Ground", 3 D2+ "High-speed ESD clamp provides ESD protection to the high-speed differential data line.", 4 D2- "High-speed ESD clamp provides ESD protection to the high-speed differential data line.", 5 VCC (power) "Supply", 6 D1- "High-speed ESD clamp provides ESD protection to the high-speed differential data line."

## UCC27714D14
designator U?
High-Speed Low-side Gate Driver Device, D0014A; Alternate Manufacturer: None; Manufacturer: Texas Instruments; SymbolCreator: a0411947; CompType: IC; U/M: EA
footprint D0014A_N
footprint D0014A_M
footprint D0014A_L
footprint D0014A_N (SOIC, 14-Leads, Body 8.7x3.9mm, Pitch 1.27mm, IPC Medium Density)
footprint D0014A_N (SOIC, 14-Leads, Body 8.7x3.9mm, Pitch 1.27mm, IPC Medium Density)
pins: 1 HI (in), 2 LI (in), 3 VSS (power), 4 NC/EN, 5 COM (power), 6 LO (power), 7 VDD (power), 8 NC, 9 NC, 10 NC, 11 HS (power), 12 HO (power), 13 HB (power), 14 NC

## URU2G330MRD
designator C?  ValueDisplayed: 33µF  (hidden comment: URU2G330MRD)
CAP, AL, 33 µF, 400 V, +/- 20%, TH; Manufacturer: Nichicon; Polarized: Y; CompType: Capacitor; Value: 33uF; U/M: EA; Cap_F: 0.000033; Tolerance_%: 20; Value1: Unknown; VDC_V: 400; Value2: 400V; IRMS_A: 0.28; TaMin_C: -40; TaMax_C: 85; Cap_Case: RCAP, 25x12.5mm
signal-integrity model Cap
simulation model Cap
footprint CAPPRD1250W100D2500H1250
pins: 1 +, 2 -

## URZ1E220MDD1TD
designator C?  ValueDisplayed: 22 µF  (hidden comment: URZ1E220MDD1TD)
CAP, AL, 22uF, 25V, +/-20%, TH; Manufacturer: Nichicon; Polarized: Y; CompType: Capacitor; U/M: EA; Cap_F: 0.000022; Tolerance_%: 20; Value1: Unknown; VDC_V: 25; IRMS_A: 0.055; TaMin_C: -55; TaMax_C: 105; Cap_Case: 5x9mm
signal-integrity model Cap
simulation model Cap
footprint RZ_500x900
pins: 1 +, 2 -

## US1M-13-F
designator D?
Diode, Ultrafast, 1000V, 1A, SMA; Manufacturer: Diodes Inc.; U/M: EA; Vf_V: 1.7; Value2: 1.7V; Io_A: 1; Vr_V: 1000; TJmax_C: 150; RJC_CperW: 30
signal-integrity model Diode
footprint SMA
pins: 1 K, 2 A

## VJ1812Y104KXEAT5Z
designator C?  ValueDisplayed: 0.1µF  (hidden comment: VJ1812Y104KXEAT5Z)
CAP, CERM, 0.1 µF, 500 V, +/- 10%, X7R, 1812; Manufacturer: Vishay-Vitramon; Polarized: N; CompType: Capacitor; Value: 0.1uF; U/M: EA; Cap_F: 0.0000001; Tolerance_%: 10; Value1: Unknown; VDC_V: 500; Value2: 500V; TaMin_C: -55; TaMax_C: 125; Cap_Case: 1812
signal-integrity model Cap
simulation model Cap
footprint 1812
footprint 1812M
footprint 1812L
footprint 1812_HV
pins: 1, 2

## VY2472M49Y5US63V7
designator C?  ValueDisplayed: 4700pF  (hidden comment: VY2472M49Y5US63V7)
CAP, CERM, 4700 pF, 440 V, +/- 20%, Y5U, TH, 12.5x5mm; Manufacturer: Vishay-Bccomponents; Polarized: N; CompType: Capacitor; Value: 4700pF; U/M: EA; Cap_F: 0.0000000047; Tolerance_%: 20; Value1: Unknown; VDC_V: 440; Value2: 440V; TaMin_C: -40; TaMax_C: 125; Cap_Case: 12.5x5x16.5
signal-integrity model Cap
simulation model Cap
footprint VY2_1250x500x1650
pins: 1, 2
